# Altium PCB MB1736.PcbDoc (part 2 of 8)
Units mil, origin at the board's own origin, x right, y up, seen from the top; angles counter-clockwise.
Board outline 5905.51 x 3779.53 mil, 6 copper layers (Top Layer, L2_GND, L3_SIG, L4_VCC, L5_GND, Bottom Layer), stack 117.811 mil thick; 481 components, 387 nets, 1904 pads, 1200 vias.
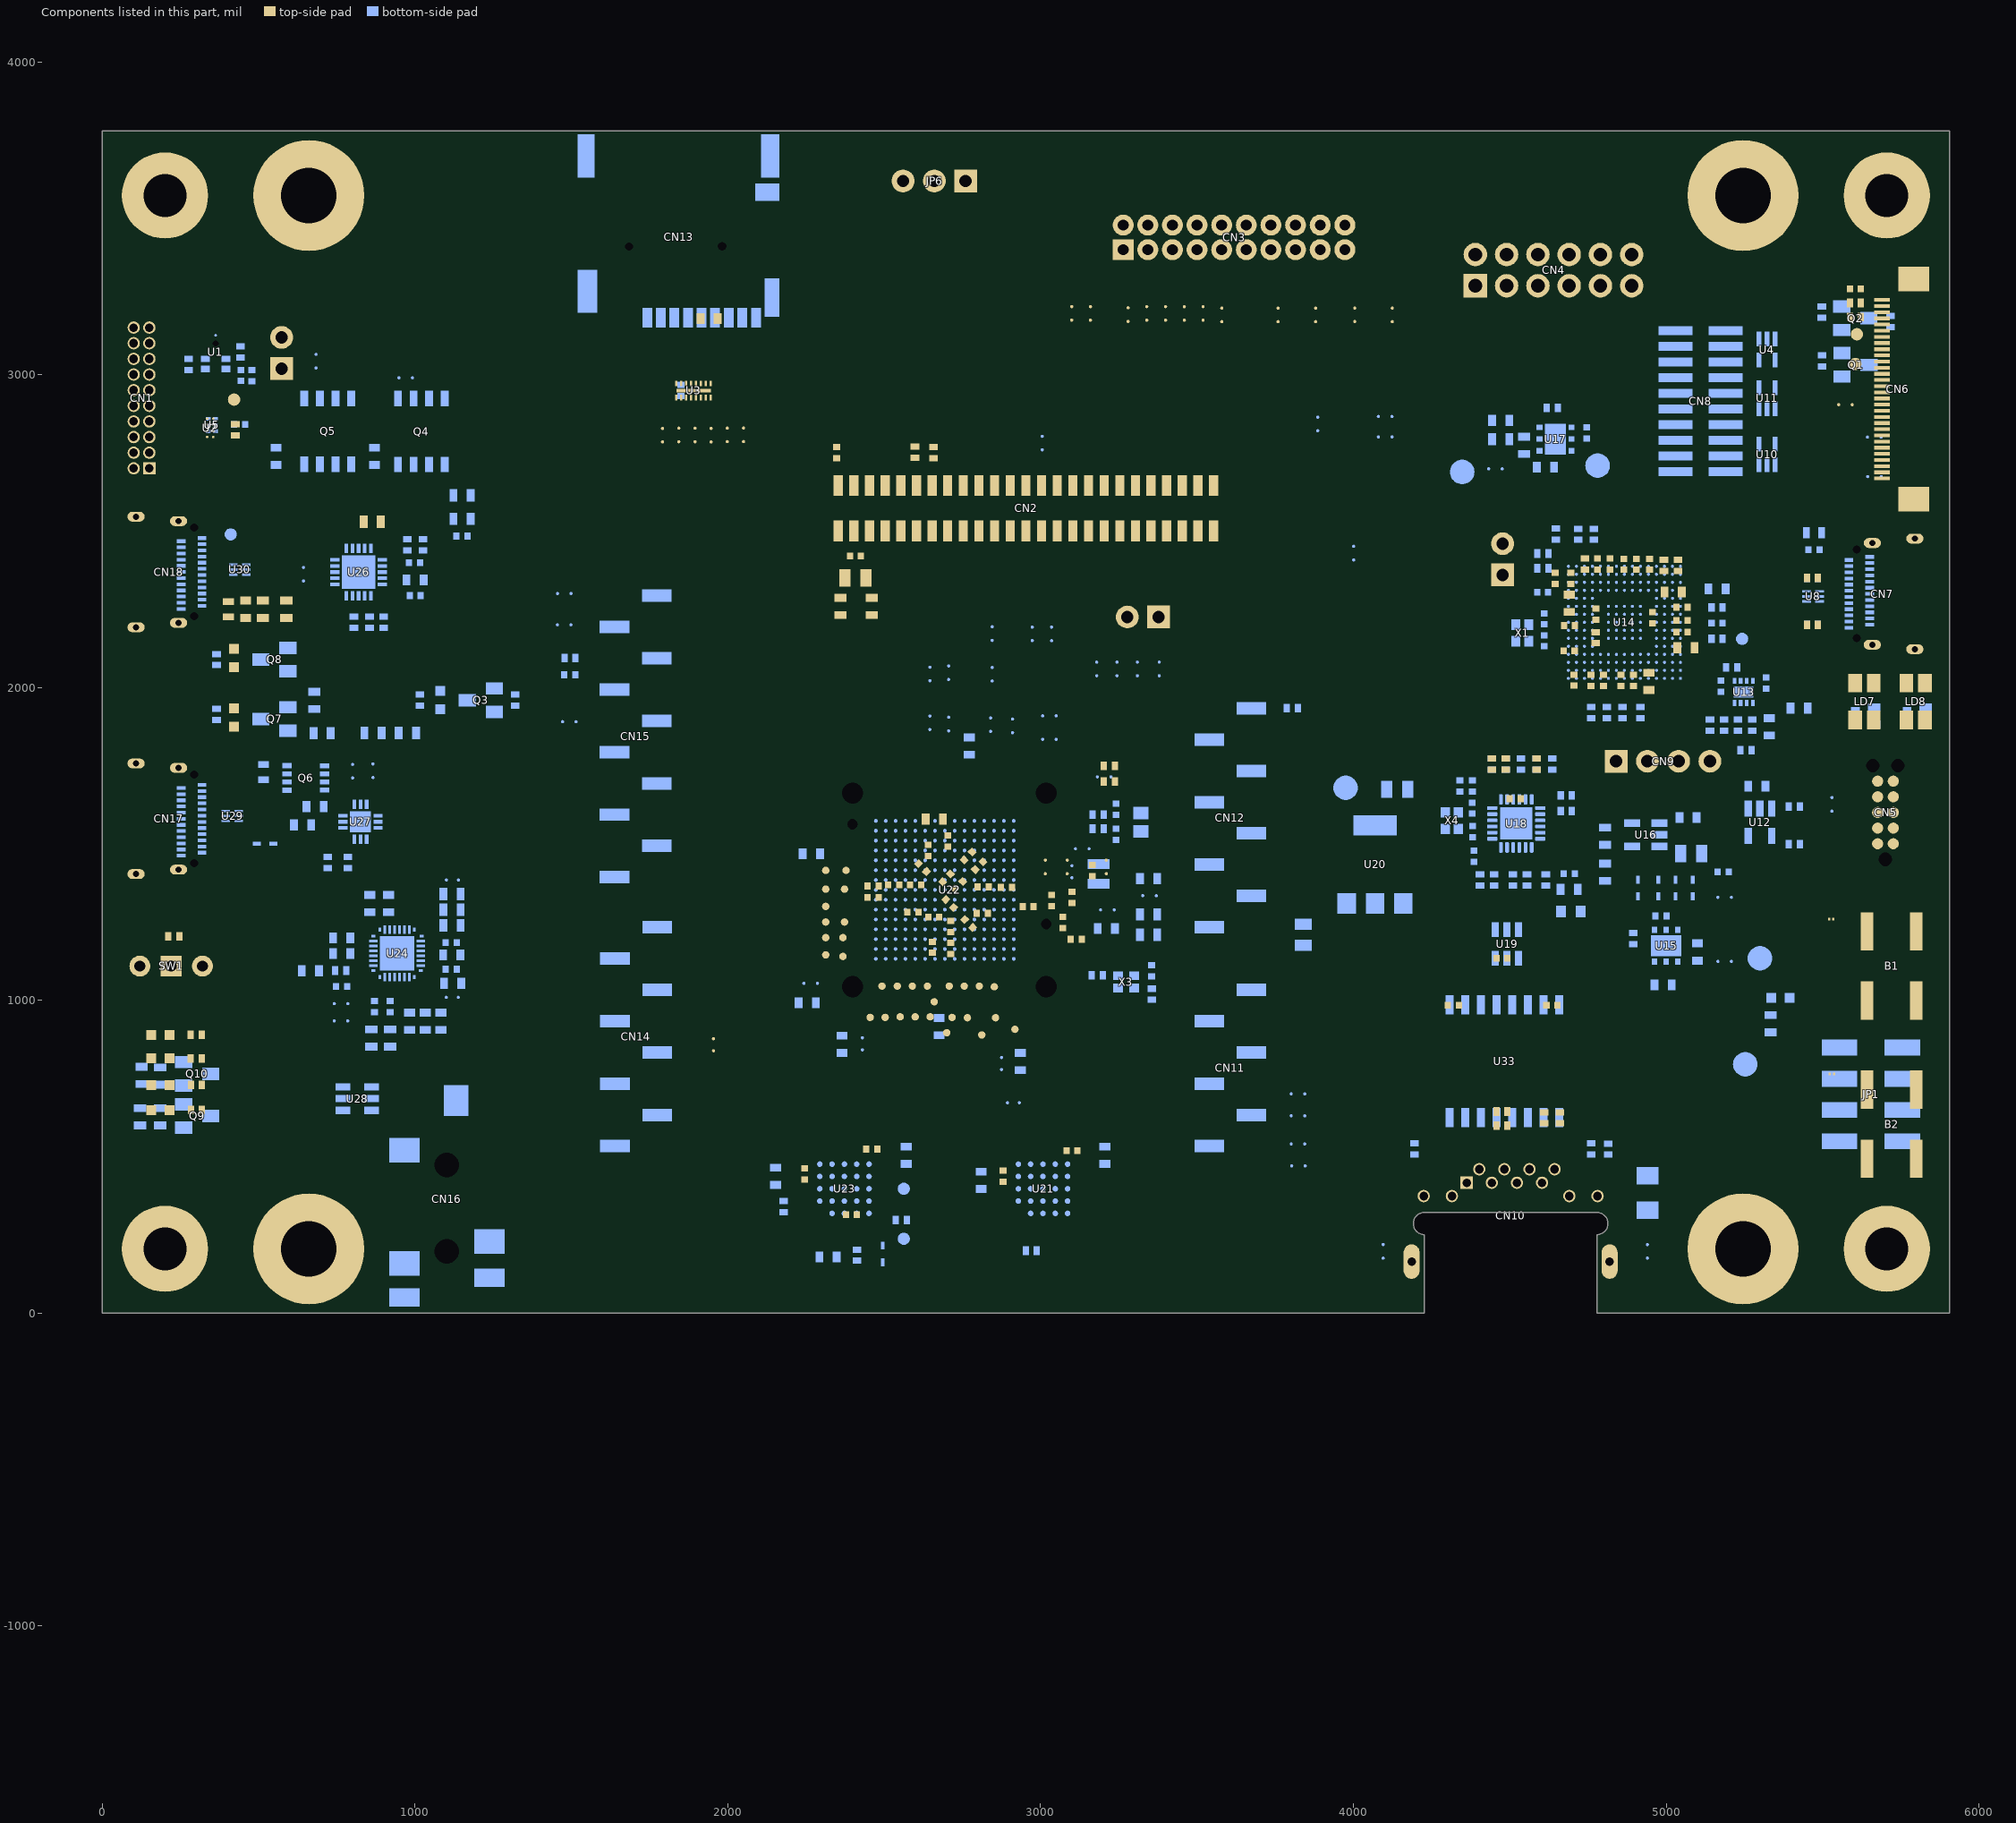
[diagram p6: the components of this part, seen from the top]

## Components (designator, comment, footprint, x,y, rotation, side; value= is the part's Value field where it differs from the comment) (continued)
TP38 "Test Point" TP_SMD_0-6MM 2367.76,1200.91 r90 top
TP39 "Test Point" TP_SMD_0-6MM 2367.76,1140.91 r90 top
TP40 "Test Point" TP_SMD_0-6MM 2372.76,1250.91 r90 top
TP41 "Test Point" TP_SMD_0-6MM 2312.76,1300.91 r90 top
TP42 "Test Point" TP_SMD_0-6MM 2312.76,1355.91 r90 top
TP43 "Test Point" TP_SMD_1MM 410,2490 r90 bottom value="Test Point 1mm"
U1 "MP23DB01MMTR" MIC_STM_MP23DB01MMTR 361.99,3072.77 r0 bottom value=MP23DB01HPTR
U2 "STG4160" ESD_FLIP-CHIP-BGA8_1P9X0P9_P050 344.6,2830.87 r270 top
U3 "EMIF06-MSD02N16" ESD_UQFN16L-EPAD_3P5X1P2_P040 1890,2950 r0 top
U4 "ESDALC6V1W5" ESD_SOT323-5L 5322.76,3080.9 r0 bottom
U5 "NX3L1T3157GM" ICC_SOT886_XSON6 350,2840 r90 bottom value=NX3L1T3157GMZ
U6 "ESD-TRANSIL" ESD_0201_H0P3_1K_2A 5527.73,1260 r180 top value=ESDZL5-1F4
U7 "ESD-TRANSIL" ESD_0201_H0P3_1K_2A 5530.02,765 r180 top value=ESDZL5-1F4
U8 "ECMF2-40A100N6" ESD_UQFN-6L_1P45X1P4_P040 5470,2292 r270 bottom
U9 "ESD-TRANSIL" ESD_QFN1610_2N_1K_2A 5472.77,2495.9 r180 bottom value=ESDA25P35-1U1M
U10 "ESDALC6V1W5" ESD_SOT323-5L 5322.76,2745.9 r180 bottom
U11 "ESDALC6V1W5" ESD_SOT323-5L 5322.76,2925.9 r180 bottom
U12 "STMPS2151STR" MOS_SOT23-5L 5300.02,1570 r0 bottom
U13 "TPS259535DSG" ICC_WSON8-EPAD_2X2_P050 5248.06,1986.67 r270 bottom
U14 "STLINK-V3EC" ICC_UFBGA201_176+25_10X10_P065 4866.64,2209.03 r0 bottom value=STM32F723IEK6
U15 "ST1L05CPU33R" ICC_DFN6-EPAD_3X3_P095 5000.02,1175.01 r0 bottom value="ST1L05CPU33R 3.3V 1.3A"
U16 "ST730M33R" ICC_SOT23-5L_H1P45 4935.01,1530 r270 bottom
U17 "ST1L05BPUR" ICC_DFN6-EPAD_3X3_P095 4646.05,2794.8 r270 bottom
U18 "LAN8742A-CZ-TR" ICC_VQFN24-EPAD_4X4_P050 4520.77,1566.11 r0 bottom
U19 "USBLC6-4SC6" ESD_SOT23-6L 4490.78,1180.73 r180 bottom
U20 "LD1117S50TR" REG_SOT223-TAB 4069.2,1435.11 r180 bottom
U21 "APS256XXN-OBR-BG" ICC_BGA24_5X5-BALL-ARRAY_6X8_P1 3007.37,398.19 r0 bottom
U22 "STM32H7S7L8H6H" ICC_TFBGA225_13X13_P080_H1P10_CODE-A0L2__SOCKET_IRONWOOD_CS1222291-D6524MF_WITHOUT-3D-SOCKET 2693.42,1353.76 r180 bottom locked
U23 "MX66UW1G45GXDI00" ICC_BGA24_5X5-BALL-ARRAY_6X8_P1 2372.52,398.19 r0 bottom
U24 "WM8904CGEFL/RV" ICC_QFN32-EPAD_4X4_P040 942.13,1150.79 r270 bottom
U26 "TCPP03-M20" ICC_QFN20-EPAD_4X4_P050 819.15,2369.73 r0 bottom
U27 "TCPP01-M12" ICC_QFN12L-EPAD_3X3_P050 825.02,1571.24 r270 bottom
U28 "ESDA6V1BC6" ESD_SOT23-6L 814.99,686.24 r270 bottom
U29 "ECMF2-40A100N6" ESD_UQFN-6L_1P45X1P4_P040 415,1590 r90 bottom
U30 "ECMF2-40A100N6" ESD_UQFN-6L_1P45X1P4_P040 439,2377.5 r90 bottom
U31 "ESD-TRANSIL" ESD_QFN1610_2N_1K_2A 402.76,2250.91 r270 top value=ESDA25P35-1U1M
U32 "ESD-TRANSIL" ESD_QFN1610_2N_1K_2A 515,1730.01 r90 bottom value=ESDA25P35-1U1M
U33 "KMS-1102NL" TRS_DGKYD_KMS-1102NL 4482.76,805.9 r0 bottom
X1 "XTAL_4_PINS" CRY_NX2016SA_4P 4540,2175 r90 bottom value=24MHz
X2 "XTAL_2_PINS" CRY_NX2012SA_2P 3320.88,1569.94 r90 bottom value=32.768KHz
X3 "OSCILLATOR_4_PINS" CRY_NZ2016SH_4P 3273.11,1059.44 r180 bottom value=24MHz
X4 "XTAL_4_PINS" CRY_NX2016SA_4P 4315,1574.99 r90 bottom value=25MHz

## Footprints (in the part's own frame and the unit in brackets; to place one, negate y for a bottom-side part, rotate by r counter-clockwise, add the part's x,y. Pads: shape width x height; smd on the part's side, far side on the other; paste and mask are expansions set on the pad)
C0402 [mm]
  rect 0.51x0.56 smd mask+0.05: 1(-0.45,0) 2(0.45,0)
  body extent -0.5,-0.3 0.5,0.3, height 0.4
C0603 [mm]
  rect 0.64x0.89 smd mask+0.05: 1(-0.7,0) 2(0.7,0)
  silkscreen extent -1.05,-0.55 1.02,0.55, body extent -0.9,-0.5 0.9,0.5, height 1.4
C0603_H0P8 [mm] "MCD-01540"
  rect 0.64x0.89 smd mask+0.05: 1(-0.7,0) 2(0.7,0)
  silkscreen extent -0.9,-0.55 0.9,0.55, body extent -0.9,-0.5 0.9,0.5, height 1
C0805 [mm]
  rect 0.9x1.4 smd mask+0.05: 1(-0.85,0) 2(0.85,0)
  silkscreen extent -1.3,-0.77 1.3,0.77, body extent -1.1,-0.7 1.1,0.7, height 1.35
C1206_H1P6 [mm]
  rect 1.4x1.78 smd mask+0.05: 1(-1.4,0) 2(1.4,0)
  silkscreen extent -2.12,-0.97 2.15,0.97, body extent -1.7,-0.9 1.7,0.9, height 1.8
CON_FCI_20021311-XXX20XXLF [mm]
  rect 1x1 / inner round 1 / far side rect 1x1 hole 0.7 mask+0.05: 1(5.715,0.635)
  round 1 hole 0.7 mask+0.05: 2(5.715,-0.635) 3(4.445,0.635) 4(4.445,-0.635) 5(3.175,0.635) 6(3.175,-0.635) 7(1.905,0.635) 8(1.905,-0.635) 9(0.635,0.635) 10(0.635,-0.635) 11(-0.635,0.635) 12(-0.635,-0.635) 13(-1.905,0.635) 14(-1.905,-0.635) 15(-3.175,0.635) 16(-3.175,-0.635) 17(-4.445,0.635) 18(-4.445,-0.635) 19(-5.715,0.635) 20(-5.715,-0.635)
  silkscreen extent -6.58,-1.5 6.58,1.5, body extent -6.58,-1.5 6.58,1.5, height 4.4
CON_MICROSD_YAMAICHI_PJS008-2003-1 [mm] "WITH POSITIONNING PINS"
  rect 1.6x0.8 smd paste+0 mask+0.05: 1(-15.6,-2.525) 2(-15.6,-1.425) 3(-15.6,-0.325) 4(-15.6,0.775) 5(-15.6,1.875) 6(-15.6,2.975) 7(-15.6,4.075) 8(-15.6,5.175) 9(-15.6,6.325)
  rect 1.4x1.95 smd paste+0 mask+0.05: 10(-5.4,7.225)
  rect 3.5x1.5 smd paste+0 mask+0.05: 11(-2.45,7.45)
  rect 3.5x1.4 smd paste+0 mask+0.05: 12(-2.45,-7.5)
  rect 3.5x1.6 smd paste+0 mask+0.05: 13(-13.45,-7.4)
  rect 3.1x1.2 smd paste+0 mask+0.05: 14(-13.95,7.6)
  round 0 hole 0.65 unplated mask+0.05: NPTH1(-9.8,-4)
  round 0 hole 0.7 unplated mask+0.05: NPTH2(-9.8,3.55)
  silkscreen extent -15.32,-7.25 5.65,7.25, body extent -15.25,-7.25 -0.45,7.42, height 2
CON_PHONE-JACK-3P5_HY_PJ3028B [mm]
  rect 1.5x2.5 smd mask+0.05: 2(1.25,-3.45) 7(2.85,3.45)
  rect 2x2.5 smd mask+0.05: 3(4,-3.45) 4(5.8,3.45) 6(13.2,-3.45)
  rect 2.5x2 smd mask+0.05: 5(17.25,0.75)
  round 0.5 hole 2 unplated mask+0.1: MT1(5,0) MT2(12,0)
  Multi-Layer keep-out circle w0.01: c5,0 r1.25
  Multi-Layer keep-out circle w0.01: c12,0 r1.25
  silkscreen extent -0.9,-3.7 16,3, body extent -0.9,-3 16,3, height 5
CON_RJ45_DGKYD_KRJ-CB4.2GYZNL [mm] "RJ45  connector, right angle"
  rect 1x1 hole 0.7 mask+0.05: 1(3.57,10.6)
  round 1 hole 0.7 mask+0.05: 2(2.55,11.7) 3(1.53,10.6) 4(0.51,11.7) 5(-0.51,10.6) 6(-1.53,11.7) 7(-2.55,10.6) 8(-3.57,11.7) 9(7.06,9.52) 10(4.77,9.52) 11(-4.77,9.52) 12(-7.06,9.52)
  oval 1.3x2.8 hole 0.7 slot 2.2 at 90 deg mask+0.05: SH1(8.04,4.2) SH2(-8.04,4.2)
  Multi-Layer keep-out lines w0.1: 9,0 7,0 7,6.4 ccw(c7,7.3) 7,8.2 -7,8.2 ccw(c-7,7.3) -7,6.4 -7,0 -9,0
  silkscreen extent -8.23,-4.1 8.22,11.45, body extent -8.39,-4.1 8.39,11.9, height 6.85
CON_SAMTEC_FLE-125-01-G-DV [mm]
  rect 0.74x1.675 smd mask+0.05: 1(-15.24,1.843) 2(-15.24,-1.843) 3(-13.97,1.843) 4(-13.97,-1.843) 5(-12.7,1.843) 6(-12.7,-1.843) 7(-11.43,1.843) 8(-11.43,-1.843) 9(-10.16,1.843) 10(-10.16,-1.843) 11(-8.89,1.843) 12(-8.89,-1.843) 13(-7.62,1.843) 14(-7.62,-1.843) 15(-6.35,1.843) 16(-6.35,-1.843) 17(-5.08,1.843) 18(-5.08,-1.843) 19(-3.81,1.843) 20(-3.81,-1.843) 21(-2.54,1.843) 22(-2.54,-1.843) 23(-1.27,1.843) 24(-1.27,-1.843) 25(0,1.843) 26(0,-1.843) 27(1.27,1.843) 28(1.27,-1.843) 29(2.54,1.843) 30(2.54,-1.843) 31(3.81,1.843) 32(3.81,-1.843) 33(5.08,1.843) 34(5.08,-1.843) 35(6.35,1.843) 36(6.35,-1.843) 37(7.62,1.843) 38(7.62,-1.843) 39(8.89,1.843) 40(8.89,-1.843) 41(10.16,1.843) 42(10.16,-1.843) 43(11.43,1.843) 44(11.43,-1.843) 45(12.7,1.843) 46(12.7,-1.843) 47(13.97,1.843) 48(13.97,-1.843) 49(15.24,1.843) 50(15.24,-1.843)
  silkscreen extent -16.38,-1.67 15.93,2.67, body extent -15.93,-2.3 15.93,2.3, height 4.55
CON_SAMTEC_FTSH-110-01-L-DV [mm]
  rect 0.74x2.79 smd mask+0.05: 1(-5.715,-2.035) 2(-5.715,2.035) 3(-4.445,-2.035) 4(-4.445,2.035) 5(-3.175,-2.035) 6(-3.175,2.035) 7(-1.905,-2.035) 8(-1.905,2.035) 9(-0.635,-2.035) 10(-0.635,2.035) 11(0.635,-2.035) 12(0.635,2.035) 13(1.905,-2.035) 14(1.905,2.035) 15(3.175,-2.035) 16(3.175,2.035) 17(4.445,-2.035) 18(4.445,2.035) 19(5.715,-2.035) 20(5.715,2.035)
  silkscreen extent -6.35,-1.71 6.35,1.71, body extent -6.35,-2.92 6.35,2.92, height 5.97
CON_SAMTEC_SQT-110-01-F-D-RA__STMOD+ [mm] "SQT-110-01-F-D-RA (connecteur SAMTEC pour interface STMod+ femelle cot?Host) Pinning adapt?non conforme SAMTEC."
  rect 1.7x1.7 hole 0.9 mask+0.05: 1(9,1)
  round 1.7 hole 0.9 mask+0.05: 2(7,1) 3(5,1) 4(3,1) 5(1,1) 6(-1,1) 7(-3,1) 8(-5,1) 9(-7,1) 10(-9,1) 11(9,-1) 12(7,-1) 13(5,-1) 14(3,-1) 15(1,-1) 16(-1,-1) 17(-3,-1) 18(-5,-1) 19(-7,-1) 20(-9,-1)
  silkscreen extent -10.15,-8.62 10.15,0.07, body extent -10.15,-8.65 10.15,1.22, height 4
CON_SAMTEC_SSW-106-02-F-D-RA__PMOD [mm] "SSW-106-02-F-D-RA (connecteur SAMTEC pour interface PMOD femelle cot?Host) Pinning adapt?non conforme SAMTEC."
  rect 1.9x1.9 hole 1.1 mask+0.05: 1(6.35,1.27)
  round 1.9 hole 1.1 mask+0.05: 2(3.81,1.27) 3(1.27,1.27) 4(-1.27,1.27) 5(-3.81,1.27) 6(-6.35,1.27) 7(6.35,-1.27) 8(3.81,-1.27) 9(1.27,-1.27) 10(-1.27,-1.27) 11(-3.81,-1.27) 12(-6.35,-1.27)
  silkscreen extent -7.88,-11.3 7.88,0.23, body extent -7.87,-11.31 7.87,1.47, height 5.21
CON_SAMTEC_SSW-106-22-X-S-VS [mil]
  rect 40x95 smd mask+1.97: 1(250,67.5) 2(150,-67.5) 3(50,67.5) 4(-50,-67.5) 5(-150,67.5) 6(-250,-67.5)
  silkscreen extent -310,-48 310,48, body extent -310,-101 310,102, height 385
CON_SAMTEC_SSW-108-22-X-S-VS [mil]
  rect 40x95 smd mask+1.97: 1(350,67.5) 2(250,-67.5) 3(150,67.5) 4(50,-67.5) 5(-50,67.5) 6(-150,-67.5) 7(-250,67.48) 8(-350,-67.48)
  silkscreen extent -410,-48 410,48, body extent -410,-101 410,102, height 385
CON_SAMTEC_SSW-110-22-X-S-VS [mil]
  rect 40x95 smd mask+1.97: 1(450,67.5) 2(350,-67.5) 3(250,67.5) 4(150,-67.5) 5(50,67.5) 6(-50,-67.5) 7(-150,67.48) 8(-250,-67.48) 9(-350,67.48) 10(-450,-67.48)
  silkscreen extent -510,-48 510,48, body extent -510,-101 510,102, height 385
CON_SAMTEC_TSM-104-01-X-DV [mm]
  rect 1.3x2.9 smd paste+0 mask+0.05: 1(-3.81,-2.55) 2(-3.81,2.55) 3(-1.27,-2.55) 4(-1.27,2.55) 5(1.27,-2.55) 6(1.27,2.55) 7(3.81,-2.55) 8(3.81,2.55)
  silkscreen extent -5.24,-2.22 5.24,2.22, body extent -5.24,-3.85 5.24,3.85, height 9.65
CON_SAMTEC_TSW-102-07-G-S [mm]
  rect 1.85x1.85 / inner round 1.85 / far side rect 1.85x1.85 hole 1 mask+0.05: 1(-1.27,0)
  round 1.85 hole 1 mask+0.05: 2(1.27,0)
  silkscreen extent -2.58,-1.3 2.58,1.3, body extent -2.67,-1.3 2.58,1.3, height 8.38
CON_SAMTEC_TSW-103-07-F-S [mm]
  rect 1.85x1.85 / inner round 1.85 / far side rect 1.85x1.85 hole 1 mask+0.05: 1(-2.54,0)
  round 1.85 hole 1 mask+0.05: 2(0,0) 3(2.54,0)
  silkscreen extent -3.85,-1.3 3.85,1.3, body extent -3.94,-1.37 3.91,1.37, height 8.38
CON_SAMTEC_TSW-104-07-G-S [mm]
  rect 1.85x1.85 / inner round 1.85 / far side rect 1.85x1.85 hole 1 mask+0.05: 1(-3.81,0)
  round 1.85 hole 1 mask+0.05: 2(-1.27,0) 3(1.27,0) 4(3.81,0)
  silkscreen extent -5.12,-1.3 5.12,1.3, body extent -5.21,-1.37 5.18,1.37, height 8.38
CON_TAG-C_TC2050-IDC-NL [mm]
  round 0.9 smd paste+0 mask+0.05: 1(-2.54,-0.635) 2(-1.27,-0.635) 3(0,-0.635) 4(1.27,-0.635) 5(2.54,-0.635) 6(2.54,0.635) 7(1.27,0.635) 8(0,0.635) 9(-1.27,0.635) 10(-2.54,0.635)
  round 0 hole 1.1 unplated mask+0.05: 11(-3.81,0) 12(3.81,-1.015) 13(3.81,1.015)
  Multi-Layer keep-out circle w0.01: c-3.81,0 r0.75
  Multi-Layer keep-out circle w0.01: c3.81,1.015 r0.75
  Multi-Layer keep-out circle w0.01: c3.81,-1.015 r0.75
  silkscreen extent -6.22,-3.4 6.22,3.33, body extent -6.28,-3.46 6.28,3.39, height 13
CON_TOWNES_FPU330ZH-BT1D3-CA_P050 [mm]
  rect 0.3x1.25 smd mask+0.05: 1(-7.25,2.575) 2(-6.75,2.575) 3(-6.25,2.575) 4(-5.75,2.575) 5(-5.25,2.575) 6(-4.75,2.575) 7(-4.25,2.575) 8(-3.75,2.575) 9(-3.25,2.575) 10(-2.75,2.575) 11(-2.25,2.575) 12(-1.75,2.575) 13(-1.25,2.575) 14(-0.75,2.575) 15(-0.25,2.575) 16(0.25,2.575) 17(0.75,2.575) 18(1.25,2.575) 19(1.75,2.575) 20(2.25,2.575) 21(2.75,2.575) 22(3.25,2.575) 23(3.75,2.575) 24(4.25,2.575) 25(4.75,2.575) 26(5.25,2.575) 27(5.75,2.575) 28(6.25,2.575) 29(6.75,2.575) 30(7.25,2.575)
  rect 2x2.5 smd mask+0.05: 31(-8.94,0) 32(8.94,0)
  silkscreen extent -9.7,-2.9 9.7,2.3, body extent -10.25,-4.25 10.25,3, height 2.05
CON_USB-TYPEC_AMPHENOL_12401826E412A [mm] "MCD-03232"
  round 0 hole 0.65 unplated mask+0.05: 0(-3.6,0)
  round 0 hole 0.65 slot 0.95 at 0 deg unplated mask+0.05: 0(3.6,0)
  rect 0.3x0.7 smd mask+0.05: A1(-2.75,0.66) A2(-2.25,0.66) A3(-1.75,0.66) A4(-1.25,0.66) A5(-0.75,0.66) A6(-0.25,0.66) A7(0.25,0.66) A8(0.75,0.66) A9(1.25,0.66) A10(1.75,0.66) A11(2.25,0.66) A12(2.75,0.66) B1(2.5,-1.04) B2(2,-1.04) B3(1.5,-1.04) B4(1,-1.04) B5(0.5,-1.04) B6(0,-1.04) B7(-0.5,-1.04) B8(-1,-1.04) B9(-1.5,-1.04) B10(-2,-1.04) B11(-2.5,-1.04) B12(-3,-1.04)
  oval 0.8x1.4 hole 0.5 slot 1.1 at 90 deg mask+0.05: SH1(-4.13,-1.25) SH2(4.13,-1.25) SH3(-4.49,-4.7) SH4(4.49,-4.7)
  Top Layer keep-out region: -3.75,-1.95 3.75,-1.95 3.75,-7.24 -3.75,-7.24
  silkscreen extent -4.7,-9.59 4.7,0.91, body extent -4.6,-9.59 4.6,0.91, height 3.25
CRY_NX2012SA_2P [mm]
  rect 1x1.25 smd mask+0.05: 1(-0.75,0) 2(0.75,0)
  silkscreen extent -1.05,-0.75 1.05,0.75, body extent -1.05,-0.63 1.05,0.63, height 0.6
CRY_NX2016SA_4P [mm]
  rect 0.85x0.75 smd mask+0.05: 1(-0.675,-0.525) 2(0.675,-0.525) 3(0.675,0.525) 4(-0.675,0.525)
  silkscreen extent -1.22,-1.02 1.05,0.85, body extent -1.05,-0.85 1.05,0.85, height 0.7
CRY_NZ2016SH_4P [mm] "MCD-01627"
  rect 0.8x0.7 smd mask+0.05: 1(-0.65,-0.5) 2(0.65,-0.5) 3(0.65,0.5) 4(-0.65,0.5)
  silkscreen extent -1.17,-0.97 1.05,0.85, body extent -1.05,-0.85 1.05,0.85, height 0.71
DIO_SOD523_1A_2K [mm] "MCD-01677"
  rect 0.65x0.3 smd mask+0.05: 1(-0.675,0) 2(0.675,0)
  silkscreen extent -0.65,-0.45 1.05,0.55, body extent -0.85,-0.45 0.85,0.45, height 0.71
ESD_0201_H0P3_1K_2A [mm] "MCD-03501"
  rect 0.187x0.225 smd paste-0.01 mask+0.025: 1(-0.169,0) 2(0.169,0)
  silkscreen extent -0.35,-0.15 -0.35,0.15, body extent -0.3,-0.17 0.3,0.17, height 0.3
ESD_FLIP-CHIP-BGA8_1P9X0P9_P050 [mm] "IPC"
  round 0.2 smd paste+0 mask+0.05: 1(-0.75,-0.25) 2(-0.25,-0.25) 3(0.25,-0.25) 4(0.75,-0.25) 5(0.75,0.25) 6(0.25,0.25) 7(-0.25,0.25) 8(-0.75,0.25)
  silkscreen extent -1.17,-0.67 1.02,0.53, body extent -0.97,-0.48 0.97,0.48, height 0.64
ESD_QFN1610_2N_1K_2A [mm] "DFN, 2-Leads, Body 1.60x1.00mm"
  rect 0.55x0.9 smd mask+0.05: 1(-0.625,0) 2(0.625,0)
  silkscreen extent -1.02,-0.58 0.85,0.58, body extent -0.85,-0.55 0.85,0.55, height 0.6
ESD_SOT23-6L [mm]
  rect 0.6x1.2 smd mask+0.05: 1(-0.95,-1.15) 2(0,-1.15) 3(0.95,-1.15) 4(0.95,1.15) 5(0,1.15) 6(-0.95,1.15)
  silkscreen extent -1.53,-0.87 1.53,0.87, body extent -1.52,-1.5 1.52,1.5, height 1.45
ESD_SOT323-5L [mm]
  rect 0.4x1.2 smd mask+0.05: 1(-0.65,-0.85) 2(0,-0.85) 3(0.65,-0.85) 4(0.65,0.85) 5(-0.65,0.85)
  silkscreen extent -1.22,-1.21 1.22,0.77, body extent -1.15,-1.05 1.15,1.05, height 1.1
ESD_UQFN16L-EPAD_3P5X1P2_P040 [mm]
  rect 0.2x0.45 smd mask+0.05: 1(-1.4,-0.575) 2(-1,-0.575) 3(-0.6,-0.575) 4(-0.2,-0.575) 5(0.2,-0.575) 6(0.6,-0.575) 7(1,-0.575) 8(1.4,-0.575) 9(1.4,0.575) 10(1,0.575) 11(0.6,0.575) 12(0.2,0.575) 13(-0.2,0.575) 14(-0.6,0.575) 15(-1,0.575) 16(-1.4,0.575)
  rect 2.8x0.3 smd mask+0.05: EP(0,0)
  silkscreen extent -1.78,-0.63 1.78,0.63, body extent -1.78,-0.63 1.78,0.63, height 0.56
ESD_UQFN-6L_1P45X1P4_P040 [mm] "MCD-03060"
  rect 0.2x0.7 smd mask+0.05: 1(-0.4,-0.525) 2(0,-0.525) 3(0.4,-0.525) 4(0.4,0.525) 5(0,0.525) 6(-0.4,0.525)
  body extent -0.72,-0.7 0.72,0.7, height 0.51
ICC_BGA24_5X5-BALL-ARRAY_6X8_P1 [mm]
  round 0.45 smd mask+0.05: A2(-1,2) A3(0,2) A4(1,2) A5(2,2) B1(-2,1) B2(-1,1) B3(0,1) B4(1,1) B5(2,1) C1(-2,0) C2(-1,0) C3(0,0) C4(1,0) C5(2,0) D1(-2,-1) D2(-1,-1) D3(0,-1) D4(1,-1) D5(2,-1) E1(-2,-2) E2(-1,-2) E3(0,-2) E4(1,-2) E5(2,-2)
  silkscreen extent -3.05,-4.05 3.05,4.05, body extent -3.05,-4.05 3.05,4.05, height 1.2
ICC_DFN6-EPAD_3X3_P095 [mm]
  rect 0.45x0.5 smd mask+0.05: 1(-0.95,-1.3) 2(0,-1.3) 3(0.95,-1.3) 4(0.95,1.3) 5(0,1.3) 6(-0.95,1.3)
  rect 2.5x1.7 smd mask+0.05: EP(0,0)
  silkscreen extent -1.55,-1.55 1.55,1.55, body extent -1.55,-1.55 1.55,1.55, height 1
ICC_QFN12L-EPAD_3X3_P050 [mm] "MCD-01809"
  rect 0.3x0.75 smd mask+0.05: 1(-0.5,-1.425) 2(0,-1.425) 3(0.5,-1.425) 7(0.5,1.425) 8(0,1.425) 9(-0.5,1.425)
  rect 0.75x0.3 smd mask+0.05: 4(1.425,-0.5) 5(1.425,0) 6(1.425,0.5) 10(-1.425,0.5) 11(-1.425,0) 12(-1.425,-0.5)
  rect 1.7x1.7 smd mask+0.05: 13(0,0)
  silkscreen extent -1.55,-1.55 1.55,1.55, body extent -1.55,-1.55 1.55,1.55, height 0.8
ICC_QFN20-EPAD_4X4_P050 [mm] "MCD-02130"
  rect 0.75x0.3 smd mask+0.05: 1(-1.925,1) 2(-1.925,0.5) 3(-1.925,0) 4(-1.925,-0.5) 5(-1.925,-1) 11(1.925,-1) 12(1.925,-0.5) 13(1.925,0) 14(1.925,0.5) 15(1.925,1)
  rect 0.3x0.75 smd mask+0.05: 6(-1,-1.925) 7(-0.5,-1.925) 8(0,-1.925) 9(0.5,-1.925) 10(1,-1.925) 16(1,1.925) 17(0.5,1.925) 18(0,1.925) 19(-0.5,1.925) 20(-1,1.925)
  rect 2.7x2.7 smd mask+0.05: 21(0,0)
  silkscreen extent -2.07,-2.07 2.07,2.07, body extent -2.13,-2.13 2.13,2.13, height 1.01
ICC_QFN32-EPAD_4X4_P040 [mm] "MCD-03196"
  rect 0.22x0.3 smd mask+0.05: 1(-1.4,-2) 8(1.4,-1.925) 17(1.4,1.925) 24(-1.4,1.925)
  rect 0.22x0.66 smd mask+0.05: 2(-1,-1.925) 3(-0.6,-1.925) 4(-0.2,-1.925) 5(0.2,-1.925) 6(0.6,-1.925) 7(1,-1.925) 18(1,1.925) 19(0.6,1.925) 20(0.2,1.925) 21(-0.2,1.925) 22(-0.6,1.925) 23(-1,1.925)
  rect 0.3x0.22 smd mask+0.05: 9(1.925,-1.4) 16(1.925,1.4) 25(-1.925,1.4) 32(-1.925,-1.4)
  rect 0.66x0.22 smd mask+0.05: 10(1.925,-1) 11(1.925,-0.6) 12(1.925,-0.2) 13(1.925,0.2) 14(1.925,0.6) 15(1.925,1) 26(-1.925,1) 27(-1.925,0.6) 28(-1.925,0.2) 29(-1.925,-0.2) 30(-1.925,-0.6) 31(-1.925,-1)
  rect 2.8x2.8 smd mask+0.05: 33(0,0)
  Top Layer region: 1.29,-2.255 1.29,-1.595 1.35,-1.595 1.51,-1.755 1.51,-2.255
  Top Layer region: -1.29,-2.255 -1.29,-1.595 -1.35,-1.595 -1.51,-1.755 -1.51,-2.255
  Top Layer region: -2.255,-1.29 -1.595,-1.29 -1.595,-1.35 -1.755,-1.51 -2.255,-1.51
  Top Layer region: -2.255,1.29 -1.595,1.29 -1.595,1.35 -1.755,1.51 -2.255,1.51
  Top Layer region: 2.255,1.29 1.595,1.29 1.595,1.35 1.755,1.51 2.255,1.51
  Top Layer region: 2.255,-1.29 1.595,-1.29 1.595,-1.35 1.755,-1.51 2.255,-1.51
  Top Layer region: 1.29,2.255 1.29,1.595 1.35,1.595 1.51,1.755 1.51,2.255
  Top Layer region: -1.29,2.255 -1.29,1.595 -1.35,1.595 -1.51,1.755 -1.51,2.255
  silkscreen extent -2.25,-2.25 -1.68,-1.68, body extent -2.01,-2.01 2,2.01, height 0.91
ICC_SOT23-5L_H1P45 [mm]
  rect 0.6x1.3 smd mask+0.05: 1(-0.95,-1.1) 2(0,-1.1) 3(0.95,-1.1) 4(0.95,1.1) 5(-0.95,1.1)
  silkscreen extent -1.75,-1.68 1.6,0.97, body extent -1.52,-1.25 1.52,1.25, height 1.45
ICC_SOT886_XSON6 [mm] "MCD-01514"
  rect 0.3x0.4 smd mask+0.05: 1(-0.5,-0.3) 2(0,-0.3) 3(0.5,-0.3) 4(0.5,0.3) 5(0,0.3) 6(-0.5,0.3)
  silkscreen extent -0.87,-0.65 0.77,0.53, body extent -0.75,-0.53 0.75,0.53, height 0.51
ICC_TFBGA225_13X13_P080_H1P10_CODE-A0L2__SOCKET_IRONWOOD_CS1222291-D6524MF_WITHOUT-3D-SOCKET [mm]
  round 0.3 smd mask+0.05: A1(-5.6,5.6) A2(-4.8,5.6) A3(-4,5.6) A4(-3.2,5.6) A5(-2.4,5.6) A6(-1.6,5.6) A7(-0.8,5.6) A8(0,5.6) A9(0.8,5.6) A10(1.6,5.6) A11(2.4,5.6) A12(3.2,5.6) A13(4,5.6) A14(4.8,5.6) A15(5.6,5.6) B1(-5.6,4.8) B2(-4.8,4.8) B3(-4,4.8) B4(-3.2,4.8) B5(-2.4,4.8) B6(-1.6,4.8) B7(-0.8,4.8) B8(0,4.8) B9(0.8,4.8) B10(1.6,4.8) B11(2.4,4.8) B12(3.2,4.8) B13(4,4.8) B14(4.8,4.8) B15(5.6,4.8) C1(-5.6,4) C2(-4.8,4) C3(-4,4) C4(-3.2,4) C5(-2.4,4) C6(-1.6,4) C7(-0.8,4) C8(0,4) C9(0.8,4) C10(1.6,4) C11(2.4,4) C12(3.2,4) C13(4,4) C14(4.8,4) C15(5.6,4) D1(-5.6,3.2) D2(-4.8,3.2) D3(-4,3.2) D4(-3.2,3.2) D5(-2.4,3.2) D6(-1.6,3.2) D7(-0.8,3.2) D8(0,3.2) D9(0.8,3.2) D10(1.6,3.2) D11(2.4,3.2) D12(3.2,3.2) D13(4,3.2) D14(4.8,3.2) D15(5.6,3.2) E1(-5.6,2.4) E2(-4.8,2.4) E3(-4,2.4) E4(-3.2,2.4) E5(-2.4,2.4) E6(-1.6,2.4) E7(-0.8,2.4) E8(0,2.4) E9(0.8,2.4) E10(1.6,2.4) E11(2.4,2.4) E12(3.2,2.4) E13(4,2.4) E14(4.8,2.4) E15(5.6,2.4) F1(-5.6,1.6) F2(-4.8,1.6) F3(-4,1.6) F4(-3.2,1.6) F5(-2.4,1.6) F6(-1.6,1.6) F7(-0.8,1.6) F8(0,1.6) F9(0.8,1.6) F10(1.6,1.6) F11(2.4,1.6) F12(3.2,1.6) F13(4,1.6) F14(4.8,1.6) F15(5.6,1.6) G1(-5.6,0.8) G2(-4.8,0.8) G3(-4,0.8) G4(-3.2,0.8) G5(-2.4,0.8) G6(-1.6,0.8) G7(-0.8,0.8) G8(0,0.8) G9(0.8,0.8) G10(1.6,0.8) G11(2.4,0.8) G12(3.2,0.8) G13(4,0.8) G14(4.8,0.8) G15(5.6,0.8) H1(-5.6,0) H2(-4.8,0) H3(-4,0) H4(-3.2,0) H5(-2.4,0) H6(-1.6,0) H7(-0.8,0) H8(0,0) H9(0.8,0) H10(1.6,0) H11(2.4,0) H12(3.2,0) H13(4,0) H14(4.8,0) H15(5.6,0) J1(-5.6,-0.8) J2(-4.8,-0.8) J3(-4,-0.8) J4(-3.2,-0.8) J5(-2.4,-0.8) J6(-1.6,-0.8) J7(-0.8,-0.8) J8(0,-0.8) J9(0.8,-0.8) J10(1.6,-0.8) J11(2.4,-0.8) J12(3.2,-0.8) J13(4,-0.8) J14(4.8,-0.8) J15(5.6,-0.8) K1(-5.6,-1.6) K2(-4.8,-1.6) K3(-4,-1.6) K4(-3.2,-1.6) K5(-2.4,-1.6) K6(-1.6,-1.6) K7(-0.8,-1.6) K8(0,-1.6) K9(0.8,-1.6) K10(1.6,-1.6) K11(2.4,-1.6) K12(3.2,-1.6) K13(4,-1.6) K14(4.8,-1.6) K15(5.6,-1.6) L1(-5.6,-2.4) L2(-4.8,-2.4) L3(-4,-2.4) L4(-3.2,-2.4) L5(-2.4,-2.4) L6(-1.6,-2.4) L7(-0.8,-2.4) L8(0,-2.4) L9(0.8,-2.4) L10(1.6,-2.4) L11(2.4,-2.4) L12(3.2,-2.4) L13(4,-2.4) L14(4.8,-2.4) L15(5.6,-2.4) M1(-5.6,-3.2) M2(-4.8,-3.2) M3(-4,-3.2) M4(-3.2,-3.2) M5(-2.4,-3.2) M6(-1.6,-3.2) M7(-0.8,-3.2) M8(0,-3.2) M9(0.8,-3.2) M10(1.6,-3.2) M11(2.4,-3.2) M12(3.2,-3.2) M13(4,-3.2) M14(4.8,-3.2) M15(5.6,-3.2) N1(-5.6,-4) N2(-4.8,-4) N3(-4,-4) N4(-3.2,-4) N5(-2.4,-4) N6(-1.6,-4) N7(-0.8,-4) N8(0,-4) N9(0.8,-4) N10(1.6,-4) N11(2.4,-4) N12(3.2,-4) N13(4,-4) N14(4.8,-4) N15(5.6,-4) P1(-5.6,-4.8) P2(-4.8,-4.8) P3(-4,-4.8) P4(-3.2,-4.8) P5(-2.4,-4.8) P6(-1.6,-4.8) P7(-0.8,-4.8) P8(0,-4.8) P9(0.8,-4.8) P10(1.6,-4.8) P11(2.4,-4.8) P12(3.2,-4.8) P13(4,-4.8) P14(4.8,-4.8) P15(5.6,-4.8) R1(-5.6,-5.6) R2(-4.8,-5.6) R3(-4,-5.6) R4(-3.2,-5.6) R5(-2.4,-5.6) R6(-1.6,-5.6) R7(-0.8,-5.6) R8(0,-5.6) R9(0.8,-5.6) R10(1.6,-5.6) R11(2.4,-5.6) R12(3.2,-5.6) R13(4,-5.6) R14(4.8,-5.6) R15(5.6,-5.6)
  round 0 hole 0.85 unplated mask+0.05: NPTH1(7.487,5.322) NPTH2(-8.238,-2.783)
  round 0 hole 1.71 unplated mask+0.05: PTH1(-8.238,7.862) PTH2(7.487,7.862) PTH3(7.487,-7.863) PTH4(-8.238,-7.863)
  silkscreen extent -9.65,-9.13 8.75,9.28, body extent -6.55,-6.55 6.55,6.55, height 1.11
ICC_UFBGA201_176+25_10X10_P065 [mm] "IPC"
  round 0.25 smd mask+0.038: A1(-4.55,4.55) A2(-3.9,4.55) A3(-3.25,4.55) A4(-2.6,4.55) A5(-1.95,4.55) A6(-1.3,4.55) A7(-0.65,4.55) A8(0,4.55) A9(0.65,4.55) A10(1.3,4.55) A11(1.95,4.55) A12(2.6,4.55) A13(3.25,4.55) A14(3.9,4.55) A15(4.55,4.55) B1(-4.55,3.9) B2(-3.9,3.9) B3(-3.25,3.9) B4(-2.6,3.9) B5(-1.95,3.9) B6(-1.3,3.9) B7(-0.65,3.9) B8(0,3.9) B9(0.65,3.9) B10(1.3,3.9) B11(1.95,3.9) B12(2.6,3.9) B13(3.25,3.9) B14(3.9,3.9) B15(4.55,3.9) C1(-4.55,3.25) C2(-3.9,3.25) C3(-3.25,3.25) C4(-2.6,3.25) C5(-1.95,3.25) C6(-1.3,3.25) C7(-0.65,3.25) C8(0,3.25) C9(0.65,3.25) C10(1.3,3.25) C11(1.95,3.25) C12(2.6,3.25) C13(3.25,3.25) C14(3.9,3.25) C15(4.55,3.25) D1(-4.55,2.6) D2(-3.9,2.6) D3(-3.25,2.6) D4(-2.6,2.6) D5(-1.95,2.6) D6(-1.3,2.6) D7(-0.65,2.6) D8(0,2.6) D9(0.65,2.6) D10(1.3,2.6) D11(1.95,2.6) D12(2.6,2.6) D13(3.25,2.6) D14(3.9,2.6) D15(4.55,2.6) E1(-4.55,1.95) E2(-3.9,1.95) E3(-3.25,1.95) E4(-2.6,1.95) E12(2.6,1.95) E13(3.25,1.95) E14(3.9,1.95) E15(4.55,1.95) F1(-4.55,1.3) F2(-3.9,1.3) F3(-3.25,1.3) F4(-2.6,1.3) F6(-1.3,1.3) F7(-0.65,1.3) F8(0,1.3) F9(0.65,1.3) F10(1.3,1.3) F12(2.6,1.3) F13(3.25,1.3) F14(3.9,1.3) F15(4.55,1.3) G1(-4.55,0.65) G2(-3.9,0.65) G3(-3.25,0.65) G4(-2.6,0.65) G6(-1.3,0.65) G7(-0.65,0.65) G8(0,0.65) G9(0.65,0.65) G10(1.3,0.65) G12(2.6,0.65) G13(3.25,0.65) G14(3.9,0.65) G15(4.55,0.65) H1(-4.55,0) H2(-3.9,0) H3(-3.25,0) H4(-2.6,0) H6(-1.3,0) H7(-0.65,0) H8(0,0) H9(0.65,0) H10(1.3,0) H12(2.6,0) H13(3.25,0) H14(3.9,0) H15(4.55,0) J1(-4.55,-0.65) J2(-3.9,-0.65) J3(-3.25,-0.65) J4(-2.6,-0.65) J6(-1.3,-0.65) J7(-0.65,-0.65) J8(0,-0.65) J9(0.65,-0.65) J10(1.3,-0.65) J12(2.6,-0.65) J13(3.25,-0.65) J14(3.9,-0.65) J15(4.55,-0.65) K1(-4.55,-1.3) K2(-3.9,-1.3) K3(-3.25,-1.3) K4(-2.6,-1.3) K6(-1.3,-1.3) K7(-0.65,-1.3) K8(0,-1.3) K9(0.65,-1.3) K10(1.3,-1.3) K12(2.6,-1.3) K13(3.25,-1.3) K14(3.9,-1.3) K15(4.55,-1.3) L1(-4.55,-1.95) L2(-3.9,-1.95) L3(-3.25,-1.95) L4(-2.6,-1.95) L12(2.6,-1.95) L13(3.25,-1.95) L14(3.9,-1.95) L15(4.55,-1.95) M1(-4.55,-2.6) M2(-3.9,-2.6) M3(-3.25,-2.6) M4(-2.6,-2.6) M5(-1.95,-2.6) M6(-1.3,-2.6) M7(-0.65,-2.6) M8(0,-2.6) M9(0.65,-2.6) M10(1.3,-2.6) M11(1.95,-2.6) M12(2.6,-2.6) M13(3.25,-2.6) M14(3.9,-2.6) M15(4.55,-2.6) N1(-4.55,-3.25) N2(-3.9,-3.25) N3(-3.25,-3.25) N4(-2.6,-3.25) N5(-1.95,-3.25) N6(-1.3,-3.25) N7(-0.65,-3.25) N8(0,-3.25) N9(0.65,-3.25) N10(1.3,-3.25) N11(1.95,-3.25) N12(2.6,-3.25) N13(3.25,-3.25) N14(3.9,-3.25) N15(4.55,-3.25) P1(-4.55,-3.9) P2(-3.9,-3.9) P3(-3.25,-3.9) P4(-2.6,-3.9) P5(-1.95,-3.9) P6(-1.3,-3.9) P7(-0.65,-3.9) P8(0,-3.9) P9(0.65,-3.9) P10(1.3,-3.9) P11(1.95,-3.9) P12(2.6,-3.9) P13(3.25,-3.9) P14(3.9,-3.9) P15(4.55,-3.9) R1(-4.55,-4.55) R2(-3.9,-4.55) R3(-3.25,-4.55) R4(-2.6,-4.55) R5(-1.95,-4.55) R6(-1.3,-4.55) R7(-0.65,-4.55) R8(0,-4.55) R9(0.65,-4.55) R10(1.3,-4.55) R11(1.95,-4.55) R12(2.6,-4.55) R13(3.25,-4.55) R14(3.9,-4.55) R15(4.55,-4.55)
  silkscreen extent -5.22,-5.07 5.07,5.23, body extent -5.07,-5.07 5.07,5.07, height 0.61
ICC_VQFN24-EPAD_4X4_P050 [mm]
  rrect50% 0.85x0.3 smd mask+0.05: 1(-1.95,1.25) 2(-1.95,0.75) 3(-1.95,0.25) 4(-1.95,-0.25) 5(-1.95,-0.75) 6(-1.95,-1.25) 13(1.95,-1.25) 14(1.95,-0.75) 15(1.95,-0.25) 16(1.95,0.25) 17(1.95,0.75) 18(1.95,1.25)
  rrect50% 0.3x0.85 smd mask+0.05: 7(-1.25,-1.95) 8(-0.75,-1.95) 9(-0.25,-1.95) 10(0.25,-1.95) 11(0.75,-1.95) 12(1.25,-1.95) 19(1.25,1.95) 20(0.75,1.95) 21(0.25,1.95) 22(-0.25,1.95) 23(-0.75,1.95) 24(-1.25,1.95)
  rect 2.6x2.6 smd paste-10 mask+0.05: EP(0,0)
  silkscreen extent -2,-2 2,2, body extent -2.05,-2.05 2.05,2.05, height 1.1
ICC_WSON8-EPAD_2X2_P050 [mm] "MCD-02194"
  rect 0.5x0.3 smd paste+0 mask+0.05: 1(-0.9,0.75) 2(-0.9,0.25) 3(-0.9,-0.25) 4(-0.9,-0.75) 5(0.9,-0.75) 6(0.9,-0.25) 7(0.9,0.25) 8(0.9,0.75)
  rect 0.9x1.6 smd paste+0 mask+0.05: 9(0,0)
  silkscreen extent -0.5,-1 0.5,1, body extent -1,-1 1,1, height 0.81
IND_2016_MURATA_LQM2MPN2R2NG0 [mm]
  rect 0.8x1.8 smd mask+0.05: 1(-0.8,0) 2(0.8,0)
  silkscreen extent -0.28,-0.87 0.28,0.87, body extent -1.07,-0.87 1.08,0.87, height 1
L0603 [mm]
  rect 0.8x0.95 smd mask+0.05: 1(-0.8,0) 2(0.8,0)
  silkscreen extent -1.33,-0.6 1.33,0.6, body extent -0.87,-0.47 0.87,0.47, height 0.95
LED_0603_OSRAM_LB-Q39G-L2OO-35-1_BLUE_1A2K_H0P4 [mm]
  rect 0.8x0.8 smd mask+0.05: 1(-0.75,0) 2(0.75,0)
  silkscreen extent -0.85,-0.53 1.28,0.53, body extent -0.85,-0.45 0.85,0.45, height 0.6
LED_0603_OSRAM_LG-Q396-PS-35_GREEN_1A2K_H0P4 [mm]
  rect 0.8x0.8 smd mask+0.05: 1(-0.75,0) 2(0.75,0)
  silkscreen extent -0.85,-0.53 1.28,0.53, body extent -0.85,-0.45 0.85,0.45, height 0.6
LED_0603_OSRAM_LO-Q976-PS-25_ORANGE_1A2K_H0P8 [mm]
  rect 0.8x0.8 smd mask+0.05: 1(-0.75,0) 2(0.75,0)
  silkscreen extent -0.85,-0.53 1.28,0.53, body extent -0.85,-0.45 0.85,0.45, height 0.8
LED_0603_VISHAY_VLMS1300-GS08_RED_1A2K_H0P8 [mm]
  rect 0.8x0.8 smd mask+0.05: 1(-0.75,0) 2(0.75,0)
  silkscreen extent -0.85,-0.53 1.28,0.53, body extent -0.85,-0.45 0.85,0.45, height 0.8
LED_BI-GR_WE-150141SV73110 [mm] "MCD-02631"
  rect 1.1x1.5 smd mask+0.05: 1(-0.75,1.5) 2(0.75,1.5) 3(-0.75,-1.5) 4(0.75,-1.5)
  silkscreen extent -1.65,-1.85 1.5,1.7, body extent -1.5,-1.85 1.5,1.85, height 2.1
MIC_STM_MP23DB01MMTR [mm]
  rect 0.725x0.522 smd mask+0.05: 1(-0.838,1.364) 2(-0.838,0.542) 4(0.838,0.542) 5(0.838,1.364)
  round 0.2 smd mask+0.05: 3(0,-1.373)
  round 0 hole 0.5 unplated mask+0.05: 6(0,-0.71)
  Top Layer circle w0.3: c0,-0.71 r0.663
  silkscreen extent -1.33,-1.75 1.33,1.75, body extent -1.33,-1.76 1.33,1.75, height 1.09
MOS_POWERFLAT_3P3X3P3_P065 [mm]
  rect 0.4x0.75 smd mask+0.05: 1(-0.975,-1.525) 2(-0.325,-1.525) 3(0.325,-1.525) 4(0.975,-1.525) 6(0.325,1.525) 7(-0.325,1.525)
  rect 0.45x0.75 smd mask+0.05: 5(1,1.525) 8(-1,1.525)
  Top Layer region: -1.755,0.2 -1.755,-0.2 -1.225,-0.2 -1.225,-0.5 1.225,-0.5 1.225,-0.2 1.755,-0.2 1.755,0.2 1.225,0.2 1.225,1.9 -1.225,1.9 -1.225,0.2
  silkscreen extent -1.63,-1.55 1.63,1.55, body extent -1.75,-1.75 1.75,1.75, height 0.91
MOS_SOT23 [mm]
  rect 1x1.4 smd mask+0.05: 1(-0.95,-1.1) 2(0.95,-1.1) 3(0,1.1)
  silkscreen extent -1.63,-0.82 1.63,0.82, body extent -1.56,-1.25 1.56,1.25, height 1.1
MOS_SOT23-5L [mm]
  rect 0.6x1.3 smd mask+0.05: 1(-0.95,-1.1) 2(0,-1.1) 3(0.95,-1.1) 4(0.95,1.1) 5(-0.95,1.1)
  silkscreen extent -1.6,-0.95 1.6,0.97, body extent -1.52,-1.25 1.52,1.25, height 1.45
NPN_SOT23 [mm]
  rect 1x1.4 smd mask+0.05: 1(-0.95,-1.1) 2(0.95,-1.1) 3(0,1.1)
  silkscreen extent -1.63,-0.82 1.63,0.82, body extent -1.56,-1.25 1.56,1.25, height 1.1
PowerFLAT_5x6 [mm] "MCD-02152"
  rect 0.65x1.25 smd mask+0.05: 1(1.905,2.675) 2(0.635,2.675) 3(-0.635,2.675) 4(-1.905,2.675) 5(-1.905,-2.675) 6(-0.635,-2.675) 7(0.635,-2.675) 8(1.905,-2.675)
  Top Layer region: -0.2,-3.3 -0.95,-3.3 -0.95,-2.75 -1.575,-2.75 -1.575,-3.3 -2.3,-3.3 -2.3,-2.3 -2.7,-2.3 -2.7,-1.5 -2.3,-1.5 -2.3,0.15 -2.7,0.15 -2.7,0.975 -2.3,0.975 -2.3,1.15 -0.2,1.15
  Top Layer region: 0.2,-3.3 0.95,-3.3 0.95,-2.75 1.575,-2.75 1.575,-3.3 2.3,-3.3 2.3,-2.3 2.7,-2.3 2.7,-1.5 2.3,-1.5 2.3,0.15 2.7,0.15 2.7,0.975 2.3,0.975 2.3,1.15 0.2,1.15
  silkscreen extent -2.5,-3 2.5,3, body extent -2.6,-3.08 2.6,3.07, height 1
PTH_350_700 [mm]
  round 7 hole 3.5 mask+0.05: 1(0,0)
  silkscreen extent -3.75,-3.75 3.75,3.75
PTH_450_900 [mm] "MCD-01612"
  round 9 hole 4.5 mask+0.05: 1(0,0)
  silkscreen extent -4.75,-4.75 4.75,4.75
R0402 [mm]
  rect 0.51x0.7 smd mask+0.05: 1(-0.45,0) 2(0.45,0)
  body extent -0.52,-0.3 0.52,0.3, height 0.4
R0603 [mm]
  rect 0.64x1 smd mask+0.05: 1(-0.7,0) 2(0.7,0)
  silkscreen extent -1.05,-0.58 1.05,0.58, body extent -0.9,-0.5 0.9,0.5, height 0.56
REG_SOT223-TAB [mm]
  rect 1.5x1.65 smd mask+0.05: 1(-2.3,-3.175) 2(0,-3.175) 3(2.3,-3.175)
  rect 3.5x1.65 smd mask+0.05: 4(0,3.175)
  silkscreen extent -3.35,-2.15 3.35,2.12, body extent -3.35,-3.48 3.35,3.48, height 1.8
SOLDER-BRIDGE_R0402-0R [mil] "MCD-01619"
  round 10 smd paste-393.7: 1(-17.72,0) 2(20.67,0)
  Top Layer region: -30.51,-13.78 -30.51,13.78 -8.37,13.78 -1.48,0 -8.37,-13.78
  Top Layer region: 1.48,13.78 8.37,0 1.48,-13.78 30.51,-13.78 30.51,13.78
  silkscreen extent -33,-17 33,17, body extent -20,-12 20,12, height 14
SOLDER-BRIDGE_R0603-0R [mil]
  round 10 smd paste-393.7: 1(-19.68,0) 2(23.62,0)
  Top Layer region: -47.24,-19.69 -47.24,19.68 -15.75,19.68 3.94,0 -15.75,-19.69 -47.24,-19.69
  Top Layer region: -5.91,19.68 13.78,0 -5.91,-19.69 47.24,-19.69 47.24,19.68 -5.91,19.68
  silkscreen extent -50,-23 50,23, body extent -36,-20 36,20, height 22
STICKER_BOARD_25X9 [mil] "Sticker to mention board CPN code"
  silkscreen extent -492,-177 492,177
STICKER_PRODUCT_25X9 [mil] "Sticker to mention board CPN code"
  silkscreen extent -492,-177 492,177
SWI_C&K_KSC321JLFS_BLACK [mm] "MCD-01799"
  rect 3.1x1 smd mask+0.05: 1(-2.8,2) 2(2.8,2) 3(-2.8,-2) 4(2.8,-2)
  silkscreen extent -3.25,-3.25 3.25,3.25, body extent -3.4,-3.25 3.4,3.25, height 3.5
SWI_C&K_KSC721JLFS_BLUE [mm] "MCD-01800"
  rect 3.1x1 smd mask+0.05: 1(-2.8,2) 2(2.8,2) 3(-2.8,-2) 4(2.8,-2)
  silkscreen extent -3.25,-3.25 3.25,3.25, body extent -3.4,-3.25 3.4,3.25, height 4.3
SWI_EAO_09-03290-01_EXTENDED_STRAIGHT_BLACK [mm]
  rect 1.7x1.7 hole 0.9 mask+0.05: 1(0,0)
  round 1.7 hole 0.9 mask+0.05: 2(0,-2.54) 3(0,2.54)
  silkscreen extent -1.25,-5 1.25,5, body extent -1.25,-5 1.25,5, height 7.9
TP_SMD_0-6MM [mm]
  round 0.6 smd paste-10 mask+0.05: 1(0,0)
  silkscreen extent -0.5,-0.5 0.5,0.5
TP_SMD_1MM [mm]
  round 1 smd paste-10 mask+0.05: 1(0,0)
  silkscreen extent -0.7,-0.7 0.7,0.7
TP_SMD_2MM [mm]
  round 2 smd paste-10 mask+0.05: 1(0,0)
  silkscreen extent -1.2,-1.2 1.2,1.2
TRS_DGKYD_KMS-1102NL [mm]
  rect 0.64x1.55 smd mask+0.05: 1(-4.445,-4.575) 2(-3.175,-4.575) 3(-1.905,-4.575) 4(-0.635,-4.575) 5(0.635,-4.575) 6(1.905,-4.575) 7(3.175,-4.575) 8(4.445,-4.575) 9(4.445,4.575) 10(3.175,4.575) 11(1.905,4.575) 12(0.635,4.575) 13(-0.635,4.575) 14(-1.905,4.575) 15(-3.175,4.575) 16(-4.445,4.575)
  silkscreen extent -6.35,-3.7 6.35,3.7, body extent -6.35,-4.7 6.35,4.7, height 6.3

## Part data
B1: library part MCD-01799, "Switch HW BLACK High3.5mm 2Newtons, BEND type", Manufacturer=C&K, Manufacturer_Part_Number=KSC321JLFS
B2: library part MCD-01800, "Switch HW BLUE High4.3mm 2.25 Newtons, BEND type", Manufacturer=C&K, Manufacturer_Part_Number=KSC721JLFS
C1 C3 C14 C15 C17 C18 C19 C20 C21 C22 C23 C24 C26 C28 C29 C30 C31 C32 C33 C34 C35 C36 C38 C39 C40 C41 C42 C46 C47 C49 C50 C51 C52 C53 C55 C56 C57 C58 C60 C62 C63 C64 C65 C67 C68 C71 C72 C73 C89 C90 C91 C92 C94 C98 C100 C107 C125 C126 C128 C129 C140 C141 C144: library part MCD-00006, "Capacitor, MLCC, 100nF, 16V, X7R, +/-10%, 0402, T=0.5mm", Manufacturer=YAGEO, Manufacturer_Part_Number=CC0402KRX7R7BB104, Package=0402
C2 C25 C37 C45 C48 C76 C99: library part MCD-01722, "Capacitor, MLCC, 1uF, 10V, X5R, +/-10%, 0402, T=0.5mm", Manufacturer=YAGEO, Manufacturer_Part_Number=CC0402KRX5R6BB105, Package=0402
C4 C145 C153 C157: library part MCD-01099, "Capacitor, MLCC, 100nF, 50V, X7R, +/-10%, 0603, T=0.8mm", Manufacturer=YAGEO, Manufacturer_Part_Number=CC0603KRX7R9BB104, Package=0603
C5 C150: library part MCD-00017, "Capacitor, MLCC, 10nF, 50V, X7R, +/-10%, 0603, T=0.8mm", Manufacturer=YAGEO, Manufacturer_Part_Number=CC0603KRX7R9BB103, Package=0603
C13 C54 C86 C88 C93 C97 C105 C110 C111 C113 C117 C118 C119 C122 C127 C133 C134 C135: library part MCD-00009, "Capacitor, MLCC, 4.7uF, 16V, X5R, +/-10%, 0603, T=0.8mm", Manufacturer=YAGEO, Manufacturer_Part_Number=CC0603KRX5R7BB475, Package=0603
C16 C103 C104: library part MCD-00014, "Capacitor, MLCC, 10uF, 25V, X5R, +/-10%, 0805, T=0.85mm", Manufacturer=YAGEO, Manufacturer_Part_Number=CC0805KRX5R8BB106, Package=0805
C27 C66 C137 C138: library part MCD-00010, "Capacitor, MLCC, 1uF, 16V, X5R, +/-10%, 0603, T=0.8mm", Manufacturer=YAGEO, Manufacturer_Part_Number=CC0603KRX5R7BB105, Package=0603
C43: library part MCD-01355, "Capacitor, MLCC, 10uF, 4V, X5R, +/-20%, 0402, T=0.5mm", Manufacturer=MURATA, Manufacturer_Part_Number=GRM155R60G106ME44, Package=0402
C44: library part MCD-01225, "Capacitor, MLCC, 220pF, 50V, NPO, +/-5%, 0402, T=0.5mm", Manufacturer=YAGEO, Manufacturer_Part_Number=CC0402JRNPO9BN221, Package=0402
C59 C61 C75 C84: library part MCD-02198, "Capacitor, MLCC, 10nF, 50V, X7R, +/-10%, 0402, T=0.5mm", Manufacturer=YAGEO, Manufacturer_Part_Number=CC0402KRX7R9BB103, Package=0402
C69 C70 C82 C114 C115 C120 C121 C130 C131 C132 C139: library part MCD-00012, "Capacitor, MLCC, 2.2uF, 10V, X5R, +/- 10%, 0603, T=0.8mm", Manufacturer=YAGEO, Manufacturer_Part_Number=CC0603KRX5R6BB225, Package=0603
C77: library part MCD-00205, "Capacitor, MLCC, 100pF, 50V, NPO, +/-5%, 0402, T=0.5mm", Manufacturer=YAGEO, Manufacturer_Part_Number=CC0402JRNPO9BN101, Package=0402
C78 C81: library part MCD-02355, "Capacitor, MLCC, 100nF, 25V, X7R, +/-10%, 0402, T=0.5mm", Manufacturer=WALSIN, Manufacturer_Part_Number=0402B104K250CT, Package=0402
C79 C80 C87 C102: library part MCD-00099, "Capacitor, MLCC, 10uF, 10V, X5R, +/-10%, 0603, T=0.8mm", Manufacturer=MURATA, Manufacturer_Part_Number=GRM188R61A106KE69D, Package=0603
C83: library part MCD-00016, "Capacitor, MLCC, 20pF, 50V, NPO, +/- 5%, 0402, T=0.5mm", Manufacturer=YAGEO, Manufacturer_Part_Number=CC0402JRNPO9BN200, Package=0402
C85: library part MCD-02372, "Capacitor, MLCC, 2.2uF, 25V, X7R, +/-10%, 0805, T=1,25mm", Manufacturer=MURATA, Manufacturer_Part_Number=GRM21BR71E225KE11L, Package=0805
C95 C96: library part MCD-01374, "Capacitor, MLCC, 5.6pF, 50V, NPO, +/-0.1pF, 0402, T=0.5mm", Manufacturer=YAGEO, Manufacturer_Part_Number=CC0402BRNPO9BN5R6, Package=0402
C101: library part MCD-00724, "Capacitor, MLCC, 470pF, 50V, NPO, +/-5%, 0402, T=0.5mm", Manufacturer=YAGEO, Manufacturer_Part_Number=CC0402JRNPO9BN471, Package=0402
C106: library part MCD-01341, "Capacitor, MLCC, 10uF, 6V3, X5R, +/-20%, 0603, T=0.8mm", Manufacturer=MURATA, Manufacturer_Part_Number=GRM188R60J106ME47D, Package=0603
C108 C109: library part MCD-01774, "Capacitor, MLCC, 2.7pF, 50V, NPO, +/-0.1pF, 0402, T=0.5mm", Manufacturer=YAGEO, Manufacturer_Part_Number=CC0402BRNPO9BN2R7, Package=0402
C136: library part MCD-00015, "Capacitor, MLCC, 10pF, 50V, NPO, +/-5%, 0402, T=0.5mm", Manufacturer=YAGEO, Manufacturer_Part_Number=CC0402JRNPO9BN100, Package=0402
C146 C147: library part MCD-03522, "Capacitor, MLCC, 560pF, 50V, NPO, +/-5%, 0402, T=0.5mm", Manufacturer=YAGEO, Manufacturer_Part_Number=CC0402JRNPO9BN561, Package=0402
C156: library part MCD-01540, "Capacitor, MLCC, 2.2uF, 50V, X5R, +/-15%, 0603,T=0.8mm", Manufacturer=MURATA, Manufacturer_Part_Number=GRM188R61H225KE11, Package=0603
C158: library part MCD-00722, "Capacitor, MLCC, 1nF, 2KV, X7R, +/-10%, 1206, T=1.25mm", Manufacturer=YAGEO, Manufacturer_Part_Number=CC1206KKX7RDBB102, Package=1206
C159 C160: library part MCD-03429, "Capacitor, MLCC, 8.2 pF, NPO, COG, 50V, +/-0.1pF, 0402, T=0.5mm", Manufacturer=MURATA, Manufacturer_Part_Number=GJM1555C1H8R2BB01D, Package=0402
CN1: library part MCD-00147, "Socket, 10x2, 1.27mm, VR, TH, T=4.30mm/2.40mm", Manufacturer="AMPHENOL ICC", Manufacturer_Part_Number=20021311-00020T4LF
CN2: library part MCD-01222, "Header, 25x2, 1.27mm, SMD, VR, T=4.55mm", Manufacturer=SAMTEC, Manufacturer_Part_Number=FLE-125-01-G-DV
CN3: library part MCD-00309, "Socket, 10x2, 2mm, RA, TH, T=6.35mm/2.29mm", Manufacturer=SAMTEC, Manufacturer_Part_Number=SQT-110-01-F-D-RA
CN4: library part MCD-00308, "Socket, 6x2, 2.54mm, RA, TH, T=8.51mm/7.62mm", Manufacturer=SAMTEC, Manufacturer_Part_Number=SSW-106-02-F-D-RA
CN5: library part MCD-00031, "Header_Plug-of-nails, 5x2, 1.27mm, No legs", Manufacturer=N/A
CN6: library part MCD-00326, "Socket_FFC/FPC, 30 pins, 0.5mm, RA, SMD, T=5.9mm", Manufacturer=TOWNES
CN7 CN17 CN18: library part MCD-03232, "USB_TypeC, 24 pins, RA, SMD, T=2.96mm", Manufacturer="AMPHENOL ICC", Manufacturer_Part_Number=12401826E412A
CN8: library part MCD-00557, "Header, 10x2, 1.27mm, VR, SMD, T=3.05mm", Manufacturer=SAMTEC, Manufacturer_Part_Number=FTSH-110-01-L-DV
CN9: library part MCD-00029, "Header, 4x1, 2.54mm, VR, TH, T=5.84mm/2.54mm", Manufacturer=SAMTEC, Manufacturer_Part_Number=TSW-104-07-G-S
CN10: library part MCD-00717, "Connector_RJ45, single port, with LEDS, T= 11.05mm", Manufacturer="DONGGUAN KEYOUDA ELECTRONIC TECHNOLOGY", Manufacturer_Part_Number=KRJ-CB4.2GYZNL
CN11: library part MCD-00299, "Socket, 6x1, 2.54mm, VR, SMD, T=9.78mm", Manufacturer=SAMTEC, Manufacturer_Part_Number=SSW-106-22-L-S-VS
CN12 CN14: library part MCD-00300, "Socket, 8x1, 2.54mm, VR, SMD, T=9.78mm", Manufacturer=SAMTEC, Manufacturer_Part_Number=SSW-108-22-L-S-VS
CN13: library part MCD-00023, "Connector_uSD Card, Reversed-Type, Mnt Push-Push", Manufacturer=YAMAICHI, Manufacturer_Part_Number=PJS008-2003-1
CN15: library part MCD-00301, "Socket, 10x1, 2.54mm, VR, SMD, T=9.78mm", Manufacturer=SAMTEC, Manufacturer_Part_Number=SSW-110-22-L-S-VS
CN16: library part MCD-00263, "Jack_ Socket-Stereo, 3.5mm, 4 pins, RA, SMD, T=5mm", Manufacturer=QIAOD, Manufacturer_Part_Number=PJ3028B-3_4P
CN19 JP3: library part MCD-00045, "Header, 2x1, 2.54mm, VR, TH, T=5.84mm/2.54mm", Manufacturer=SAMTEC, Manufacturer_Part_Number=TSW-102-07-G-S
D1 D3 D4 D5 D6 D7: library part MCD-01677, "Small signal Schottky diodes", Manufacturer=STMICROELECTRONICS, Manufacturer_HQ_COO=EU, Manufacturer_Part_Number=BAT54KFILM, Package=SOD-523
H1 H2 H3 H4: library part MCD-00328, "POSITION HOLE C7D3R5", Manufacturer=N/A
H5 H6 H7 H8: library part MCD-01612, "POSITION HOLE C9D4R5", Manufacturer=N/A
HW1: library part MCD-00547, "Sticker product 25x9 mm", Manufacturer=N/A
HW2: library part MCD-00235, "Sticker Board 25x9 mm", Manufacturer=N/A
JP1: library part MCD-00044, "Header, 4x2, 2.54mm, VR, SMD, T=5.84mm/2.54mm", Manufacturer=SAMTEC, Manufacturer_Part_Number=TSM-104-01-G-DV
JP5: library part MCD-00683, "Header, 2x1, 2.54mm, VR, TH, T=5.84mm/2.54mm", Manufacturer=SAMTEC, Manufacturer_Part_Number=TSW-102-07-G-S
JP6: library part MCD-00684, "Header, 3x1, 2.54mm, VR, TH, T=5.84mm/2.54mm", Manufacturer=SAMTEC, Manufacturer_Part_Number=TSW-103-07-F-S
L1: library part MCD-02437, "Ferrite bead, 600R@100MHz, +/-25%, 500mA, 380mR, 0603, T=0.8mm", Manufacturer=MURATA, Manufacturer_Part_Number=BLM18AG601SN1D, Package=0603
L4: library part MCD-01110, "Inductor, 2.2uH, +/-30%, 1.2A, 0R138, 0806, T=0.9mm", Manufacturer=MURATA, Manufacturer_Part_Number=LQM2MPN2R2NG0, Package=0806
LD1 LD5 LD6 LD10 LD12: library part MCD-00588, "LED Green, 0603 SMD, Forward Voltage Typ=2V, Max=2.5V", Manufacturer="OSRAM OPTO SEMICONDUCTORS", Manufacturer_Part_Number="LG Q396-PS-35", Package="LED 0603"
LD2: library part MCD-00590, "LED Orange, 0603 SMD, Forward Voltage Min=1.6V, Max=2.4V", Manufacturer="OSRAM OPTO SEMICONDUCTORS", Manufacturer_Part_Number="LO Q976-PS-25", Package="LED 0603"
LD3: library part MCD-00587, "LED Red, 0603 SMD, 2V Forward Voltage", Manufacturer=VISHAY, Manufacturer_Part_Number=VLMS1300-GS08, Package="LED 0603"
LD4: library part MCD-00585, "LED Blue, 0603 SMD, Forward Voltage Min=2,8V, Max=3,8V", Manufacturer="OSRAM OPTO SEMICONDUCTORS", Manufacturer_Part_Number="LB Q39G-L2OO-35-1", Package="LED 0603"
LD7 LD8: library part MCD-02631, "LED Bicolor, Green/Red, 2V, 20mA,  4-PLCC", Manufacturer="WURTH ELEKTRONIK", Manufacturer_Part_Number=150141SV73110, Package=4-PLCC
Q1 Q2 Q3: library part MCD-01969, "Transistor, N-channel enhancement mode field-effect transistor", Manufacturer=NEXPERIA, Manufacturer_Part_Number=BSN20BK
Q4 Q5: library part MCD-02152, "MOSFET, Dual N-channel 30 V, 0.016 Ω typ., 40 A, STripFET™ H5 Power MOSFET", Manufacturer=STMICROELECTRONICS, Manufacturer_HQ_COO=EU, Package="PowerFLAT 5x6"
Q6: library part MCD-01810, "N-channel 30 V, 6 mΩ typ, 11 A STripFET™ H6, Power MOSFET in a PowerFLAT™ 3.3x3.3 package", Manufacturer=STMICROELECTRONICS, Manufacturer_HQ_COO=EU, Package="PowerFLAT 3.3x3.3"
Q7 Q8 Q9 Q10: library part MCD-00073, "NPN Bipolar Transistor", Manufacturer="ON SEMICONDUCTOR", Manufacturer_Part_Number=BSR14, Package=SOT23
R1 R7 R8 R9 R48 R50 R61 R64 R65 R82 R85 R86 R90 R91 R93 R94 R99 R102 R104 R110 R115 R116 R117 R118 R151 R152 R159: library part MCD-00053, "Resistor, 10K, 0402, +/-1%, 1/16W", Manufacturer=YAGEO, Manufacturer_Part_Number=RC0402FR-0710KL, Package=0402
R2 R29 R32 R51 R52 R55 R57 R58 R111 R112 R120 R153 R155: library part MCD-00052, "Resistor, 0R, 0402, +/-5%, 1/16W", Manufacturer=YAGEO, Manufacturer_Part_Number=RC0402JR-070RL, Package=0402
R3: library part MCD-00507, "Resistor, 680R, 0402, +/-1%, 1/16W", Manufacturer=YAGEO, Manufacturer_Part_Number=RC0402FR-07680RL, Package=0402
R4 R5: library part MCD-00064, "Resistor, 510R, 0402, +/-1%, 1/16W", Manufacturer=YAGEO, Manufacturer_Part_Number=RC0402FR-07510RL, Package=0402
R6: library part MCD-00449, "Resistor, 300R, 0402, +/-1%, 1/16W", Manufacturer=YAGEO, Manufacturer_Part_Number=RC0402FR-07300RL, Package=0402
R17 R21 R106 R109 R127 R129 R131: library part MCD-00056, "Resistor, 0R, 0603, +/-5%, 1/10W", Manufacturer=YAGEO, Manufacturer_Part_Number=RC0603JR-070RL, Package=0603
R44 R45 R92: library part MCD-00068, "Resistor, 1K5, 0402, +/-1%, 1/16W", Manufacturer=YAGEO, Manufacturer_Part_Number=RC0402FR-071K5L, Package=0402
R46 R47 R49 R56 R73 R74 R89 R96: library part MCD-00455, "Resistor, 33R, 0402, +/-1%, 1/16W", Manufacturer=YAGEO, Manufacturer_Part_Number=RC0402FR-0733RL, Package=0402
R53 R54 R66 R68 R177: library part MCD-00059, "Resistor, 100K, 0402, +/-1%, 1/16W", Manufacturer=YAGEO, Manufacturer_Part_Number=RC0402FR-07100KL, Package=0402
R59 R62: library part MCD-00197, "Resistor, 330R, 0603, +/-1%, 1/10W", Manufacturer=YAGEO, Manufacturer_Part_Number=RC0603FR-07330RL, Package=0603
R60 R63: library part MCD-02665, "Resistor, 1K, 0402, +/-0.1%, 1/16W, +/-25ppm/°C", Manufacturer=YAGEO, Manufacturer_Part_Number=RT0402BRD071KL, Package=0402
R67 R71 R72 R88: library part MCD-00333, "Resistor, 5K1, 0402, +/-1%, 1/16W", Manufacturer=YAGEO, Manufacturer_Part_Number=RC0402FR-075K1L, Package=0402
R69: library part MCD-00374, "Resistor, 1K2, 0603, +/-1%, 1/10W", Manufacturer=YAGEO, Manufacturer_Part_Number=RC0603FR-071K2L, Package=0603
R70: library part MCD-00259, "Resistor, 33K, 0603, +/-1%, 1/10W", Manufacturer=YAGEO, Manufacturer_Part_Number=RC0603FR-0733KL, Package=0603
R75 R79: library part MCD-00185, "Resistor, 3K, 0402, +/-1%, 1/16W", Manufacturer=YAGEO, Manufacturer_Part_Number=RC0402FR-073KL, Package=0402
R76: library part MCD-02455, "Resistor, 3K9, 0402, +/-1%, 1/16W, +/-100ppm/°C", Manufacturer=YAGEO, Manufacturer_Part_Number=RC0402FR-073K9L, Package=0402
R77: library part MCD-00381, "Resistor, 1K3, 0402, +/-1%, 1/16W", Manufacturer=YAGEO, Manufacturer_Part_Number=RC0402FR-071K3L, Package=0402
R78: library part MCD-00067, "Resistor, 100R, 0402, +/- 1%, 1/16W", Manufacturer=YAGEO, Manufacturer_Part_Number=RC0402FR-07100RL, Package=0402
R80: library part MCD-00409, "Resistor, 1K8, 0402, +/-1%, 1/16W", Manufacturer=YAGEO, Manufacturer_Part_Number=RC0402FR-071K8L, Package=0402
R83 R158 R163 R170 R171: library part MCD-00222, "Resistor, 47K, 0603, 1%, 1/10W", Manufacturer=YAGEO, Manufacturer_Part_Number=RC0603FR-0747KL, Package=0603
R84 R97: library part MCD-00444, "Resistor, 27K, 0603, +/-1%, 1/10W", Manufacturer=YAGEO, Manufacturer_Part_Number=RC0603FR-0727KL, Package=0603
R87 R107 R166 R167: library part MCD-00441, "Resistor, 270R, 0402, +/-1%, 1/16W", Manufacturer=YAGEO, Manufacturer_Part_Number=RC0402FR-07270RL, Package=0402
R95 R98 R100 R103: library part MCD-00565, "Resistor, 49R9, 0402, +/-1%, 1/16W", Manufacturer=YAGEO, Manufacturer_Part_Number=RC0402FR-0749R9L, Package=0402
R101: library part MCD-00494, "Resistor, 56K, 0603, +/-1%, 1/10W", Manufacturer=YAGEO, Manufacturer_Part_Number=RC0603FR-0756KL, Package=0603
R105: library part MCD-00723, "Resistor, 12K1, 0402, +/-1%, 1/16W", Manufacturer=YAGEO, Manufacturer_Part_Number=RC0402FR-0712K1L, Package=0402
R108: library part MCD-00061, "Resistor, 1K, 0402, +/-1%,1/16W", Manufacturer=YAGEO, Manufacturer_Part_Number=RC0402FR-071KL, Package=0402
R113: library part MCD-00504, "Resistor, 62K, 0603, +/-1%, 1/10W", Manufacturer=YAGEO, Manufacturer_Part_Number=RC0603FR-0762KL, Package=0603
R114: library part MCD-00485, "Resistor, 51R, 0402, +/-1%, 1/16W", Manufacturer=YAGEO, Manufacturer_Part_Number=RC0402FR-0751RL, Package=0402
R130: library part MCD-00182, "Resistor, 1M, 0402, +/-1%, 1/16W", Manufacturer=YAGEO, Manufacturer_Part_Number=RC0402FR-071ML, Package=0402
R132: library part MCD-00057, "Resistor, 2K2, 0402, +/-1%, 1/16W", Manufacturer=YAGEO, Manufacturer_Part_Number=RC0402FR-072K2L, Package=0402
R134: library part MCD-02232, "Resistor, 22mR, 0603, +/-1%, 1/3W", Manufacturer=PANASONIC, Manufacturer_Part_Number=ERJ-3BWFR022V, Package=0603
R135: library part MCD-01171, "Resistor, 49K9, 0603, +/-1%, 1/10W", Manufacturer=YAGEO, Manufacturer_Part_Number=RC0603FR-0749K9L, Package=0603
R136: library part MCD-00458, "Resistor, 330K, 0603, +/-1%, 1/10W", Manufacturer=YAGEO, Manufacturer_Part_Number=RC0603FR-07330KL, Package=0603
R145 R146: library part MCD-00345, "Resistor, 20R, 0603, +/-1%, 1/10W", Manufacturer=YAGEO, Manufacturer_Part_Number=RC0603FR-0720RL, Package=0603
R147 R156: library part MCD-00433, "Resistor, 2K4, 0402, +/-1%, 1/16W", Manufacturer=YAGEO, Manufacturer_Part_Number=RC0402FR-072K4L, Package=0402
R150: library part MCD-00062, "Resistor, 330R, 0402, +/-1%, 1/16W", Manufacturer=YAGEO, Manufacturer_Part_Number=RC0402FR-07330RL, Package=0402
R161 R162: library part MCD-00220, "Resistor, 10K, 0603, +/-1%, 1/10W", Manufacturer=YAGEO, Manufacturer_Part_Number=RC0603FR-0710KL, Package=0603
R168 R169: library part MCD-00223, "Resistor, 100K, 0603, +/- 1%, 1/10W", Manufacturer=YAGEO, Manufacturer_Part_Number=RC0603FR-07100KL, Package=0603
R172 R173 R174 R175: library part MCD-00515, "Resistor, 75R, 0402, +/-1%, 1/16W", Manufacturer=YAGEO, Manufacturer_Part_Number=RC0402FR-0775RL, Package=0402
SB1 SB3 SB5 SB7 SB10 SB11 SB13 SB15 SB17 SB19 SB24 SB27 SB32 SB39 SB43 SB45 SB47 SB52 SB65 SB72 SB73 SB74 SB75 SB76 SB77: library part MCD-00072, "Solder Bridge OFF", Manufacturer=YAGEO, Manufacturer_Part_Number=RC0603JR-070RL, Package=SB0603
SB2 SB4 SB6 SB8 SB9 SB12 SB14 SB16 SB18 SB20 SB21 SB22 SB23 SB25 SB26 SB28 SB29 SB30 SB31 SB33 SB34 SB35 SB37 SB40 SB41 SB42 SB44 SB46 SB49 SB50 SB51 SB53 SB54 SB55 SB56 SB58 SB59 SB61 SB62 SB63 SB64 SB68 SB69 SB70 SB71: library part MCD-00071, "Solder Bridge ON", Manufacturer=YAGEO, Manufacturer_Part_Number=RC0603JR-070RL, Package=SB0603
SB36 SB38 SB48 SB57 SB60 SB66 SB67: library part MCD-01618, "Solder Bridge 0402 ON", Manufacturer=YAGEO, Manufacturer_Part_Number=RC0402JR-070RL, Package=SB0402
SW1: library part MCD-00566, "Mechanical Slide Switches 1K2 BLK ACT GOLD STRT MNT", Manufacturer=EAO, Manufacturer_Part_Number=09.03290.01
TP1 TP2 TP4 TP9 TP10 TP11 TP43: library part MCD-00074, "Test Point 1mm", Manufacturer=N/A
TP3 TP5 TP6 TP7 TP8: library part MCD-00177, "Test Point 2mm", Manufacturer=N/A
